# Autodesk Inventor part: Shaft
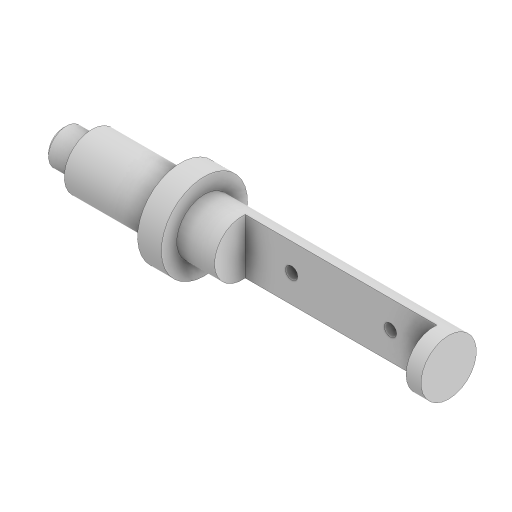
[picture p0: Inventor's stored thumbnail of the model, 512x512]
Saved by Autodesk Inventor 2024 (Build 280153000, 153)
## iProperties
Created: 2019-03
Part Number: Shaft
Material: Generic
Document SubType Name: Modeling
Designer: LENOVO-CADCIM
Density: 1 g/cm^3
Appearance: Default
Author: LENOVO-CADCIM
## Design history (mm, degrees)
sketch "Sketch1"
  geometry: L1 (284.311, 0)-(1023.188, 0); L2 (391.676, 0)-(391.676, -18); L3 (391.676, -18)-(420.576, -18); L4 (420.576, -18)-(420.576, -28); L5 (420.576, -28)-(510.376, -28); L6 (510.376, -28)-(510.376, -43.6); L7 (510.376, -43.6)-(534.376, -43.6); L8 (534.376, -43.6)-(534.376, -28); L9 (534.376, -28)-(781.476, -28); L10 (781.476, -28)-(781.476, 0); L11 (391.676, 0)-(781.476, 0); 1 further point
  constraints: 22 end point, 8 perpendicular, 5 point on line, 1 collinear, 1 horizontal
  dimensions: "d0" = 28.9 distance of L2.end L3.end; "d1" = 89.8 distance of L4.end L5.end; "d2" = 24 distance of L6.end L7.end; "d3" = 247.1 distance of L8.end L9.end; "d4" = 56 diameter of L9 L1; "d5" = 87.2 diameter of L7 L1; "d6" = 36 diameter of L3 L1
revolve "Revolution1" sketch "Sketch1" stored, may be unused: angle "d7" = 90 deg
sketch "Sketch4"
  geometry: L1 (-781.476, 28)-(-534.376, 28) reference; L2 (-572.576, 28)-(-766.376, 28); L3 (-766.376, 28)-(-766.376, -3.1); L4 (-766.376, -3.1)-(-572.576, -3.1); L5 (-572.576, -3.1)-(-572.576, 28); L6 (-781.476, -28)-(-534.376, -28) reference; 2 further points
  constraints: 8 end point, 2 parallel, 1 horizontal, 1 perpendicular, 1 point on line
  dimensions: "d16" = 24.9 distance between parallel lines of L6 L4; "d17" = 15.1 distance from line of L1.start L3; "d40" = 193.8 distance of L3.end L4.end
extrude "Extrusion3" cut sketch "Sketch4" stored distance "d18" = 257; taper "d19" = 0 deg
sketch "Sketch6"
  geometry: L1 (-180.9, 45.828)-(-180.9, 9.828) reference; L2 (-180.9, 27.828)-(320.546, 27.828); L3 (0, 55.828)-(0, -0.172) reference; 5 further points
  constraints: 2 end point, 2 point on line, 1 horizontal, 1 midpoint
  dimensions: "d24" = 100 distance of point (46.9, 27.828) point (146.9, 27.828); "d25" = 46.9 distance from line of L3 point (46.9, 27.828)
hole "Hole1" sketch "Sketch6" at (46.9, 27.828), (146.9, 27.828) diameter "d26" = 12.5; stored, may be unused: countersink angle "d30" = 90 deg, drill point angle "d32" = 118 deg; dims "d27" = 6, "d28" = 100, "d29" = 25, "d31" = 310
chamfer "Chamfer1" distance "d33" = 3; stored, may be unused: second distance "d34" = 2, angle "d35" = 45 deg
sketch "Sketch7"
  geometry: L1 (8, -22)-(-8, -22); L2 (-8, -22)-(-8, -26.833); L3 (8, -26.833)-(8, -22); L4 (0, 0)-(0, 64); C1 r 28 at (0, 0) reference; A1 r 28 centre (0, 0) between (-8, -26.833) and (8, -26.833); A2 r 28 centre (0, 0) between (8, -26.833) and (-8, -26.833) reference; 4 further points
  constraints: 8 end point, 3 point on circle, 1 centre point, 1 coincident, 1 concentric, 1 horizontal, 1 parallel, 1 perpendicular, 1 vertical, 1 other
  dimensions: "d36" = 16 distance between parallel lines of L3 L2; "d37" = 50 distance from line of point (0, 28) L1
extrude "Extrusion5" cut sketch "Sketch7" distance "d38" = 62.5; taper "d39" = 0 deg
body "Solid1"
